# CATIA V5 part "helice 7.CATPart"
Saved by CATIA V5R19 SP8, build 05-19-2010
Part number: helice 7
Bounding box of the stored display mesh (mm): x -17.321 to 17.321, y -30 to 195, z -10 to 20
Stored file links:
  G:\EU_thinkMotion\CFAO_2010\MMS_groupe2\MMS_groupe2\A reprendre\splanchenault\Planchenault\helice 7.CATPart
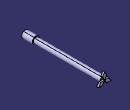
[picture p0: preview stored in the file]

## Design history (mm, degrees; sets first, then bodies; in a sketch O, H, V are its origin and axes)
Body1 (main body)
  Sketch1 on yz-plane, origin (0, 0, 0), H (0, 1, 0), V (0, 0, 1)
    line L1 (0, 0) -> (-30, 0)
    line L2 (-30, 0) -> (-30, 10)
    line L3 (-30, 10) -> (0, 10)
    line L4 (0, 10) -> (0, 7.5)
    line L5 (0, 7.5) -> (190, 7.5)
    line L6 (190, 7.5) -> (190, 0)
    point P6 (190, 0)
    line L7 (0, 0) -> (190, 0)
    length L6 = 7.5
    length L2 = 10
    length L3 = 30
    distance L4 V = 0
    length L5 = 190
    horizontal: L1 H, L3 H, L5 H, L7 H
    vertical: L2 V, L4 V, L6 V
    coincidence: P6 H
  Shaft1: profile Sketch1, axis Sketch1.L7, angle 360
  Sketch2 on face of Shaft1 from Sketch1.L6, origin (0, 190, 0), H (-1, 0, 0), V (0, 0, 1)
    construction line L1 (27.3861, -15.8114) -> (-27.3861, 15.8114)
    axis line L2 (-27.3861, -15.8114) -> (27.3861, 15.8114)
    line L3 (0, 0) -> (5.7735, 10)
    point P5 (5.7735, 10)
    line L4 (5.7735, 10) -> (0, 20)
    point P6 (0, 20)
    line L5 (0, 20) -> (-5.7735, 10)
    point P7 (-5.7735, 10)
    line L6 (-5.7735, 10) -> (0, 0)
    point P8 (11.547, 0)
    point P9 (0, 0)
    line L7 (0, 0) -> (11.547, 0)
    point P10 (5.7735, -10)
    line L8 (5.7735, -10) -> (0, 0)
    point P11 (17.3205, -10)
    line L9 (17.3205, -10) -> (5.7735, -10)
    line L10 (11.547, 0) -> (17.3205, -10)
    point P12 (-5.7735, -10)
    point P13 (0, 0)
    line L11 (0, 0) -> (-5.7735, -10)
    point P14 (-11.547, 0)
    line L12 (-11.547, 0) -> (0, 0)
    point P15 (-17.3205, -10)
    line L13 (-17.3205, -10) -> (-11.547, 0)
    line L14 (-5.7735, -10) -> (-17.3205, -10)
    angle L1 V = 60
    angle L2 V = 60
    perpendicularity: L3 L1, L4 L2
    coincidence: P6 V, O P9, O P13, P9 P13
    parallelism: L5 L3, L6 L4
    symmetry: P5 P8 L2, O P9 L2, L3 L7 L2, P7 P10 L2, L6 L8 L2, P6 P11 L2, L5 L9 L2, L4 L10 L2, P5 P12 L1, O P13 L1, L3 L11 L1, P7 P14 L1, L6 L12 L1, P6 P15 L1, L5 L13 L1, L4 L14 L1
  Pad1: profile Sketch2, direction (0, 1, 0), length 5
